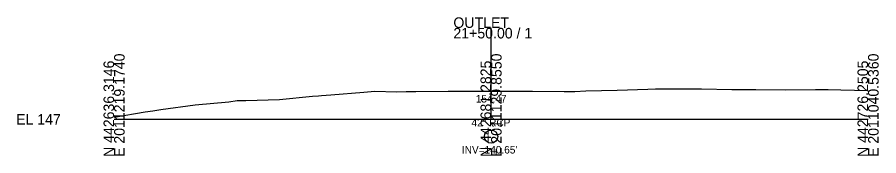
# Model space of a CAD drawing. Extents: x -26 to 1203, y -15 to 9526.
# Drawn here: x 974.3 to 1202.8, y 1490.3 to 1527.1 of the extents above; entities that cross this region are included whole.
import ezdxf

# ---------------------------------------------------------------- set-up
doc = ezdxf.new("R2010")
doc.units = 0
for name, color, linetype in [('Exist Cross Section Cell', 7, 'Continuous'), ('Exist XS Center Line Elevation Label', 7, 'Continuous'), ('Exist XS Ground Line', 7, 'Continuous'), ('Prop XSC Text', 7, 'Continuous')]:
    doc.layers.add(name, color=color, linetype=linetype)

msp = doc.modelspace()

# ---------------------------------------------------------------- linework, layer by layer
at = {"layer": 'Exist Cross Section Cell'}
for p, q in [((1100, 1500), (1100, 1524.3)), ((1000, 1500), (1100, 1500)), ((1100, 1500), (1200, 1500))]:
    msp.add_line(p, q, dxfattribs=at)
at = {"layer": 'Exist XS Ground Line'}
msp.add_lwpolyline([(1000, 1500.59), (1008.2, 1501.96), (1010.27, 1502.29), (1012.38, 1502.57), (1021.47, 1503.87), (1030.43, 1504.68), (1032.66, 1504.96), (1034.92, 1504.97), (1043.86, 1505.27), (1052.67, 1506.13), (1054.26, 1506.27), (1055.05, 1506.35), (1057.47, 1506.5), (1066.25, 1507.25), (1069.15, 1507.52), (1074.91, 1507.33), (1077.45, 1507.38), (1080.02, 1507.39), (1088.64, 1507.49), (1097.15, 1507.48), (1100, 1507.47), (1102.56, 1507.48), (1111.03, 1507.45), (1119.39, 1507.42), (1122.23, 1507.43), (1125.11, 1507.53), (1133.43, 1507.78), (1141.62, 1508.04), (1143.62, 1508.1), (1144.62, 1508.1), (1147.66, 1508.08), (1155.82, 1508.09), (1163.86, 1507.97), (1167.01, 1507.93), (1170.21, 1507.91), (1178.21, 1507.83), (1186.1, 1507.91), (1189.4, 1507.96), (1192.75, 1507.83), (1200, 1507.66)], dxfattribs=at)
at = {"layer": 'Prop XSC Text'}
msp.add_circle((1100, 1495.4), 1.75, dxfattribs=at)

# ---------------------------------------------------------------- texts
at = {"layer": 'Exist Cross Section Cell'}
for s, p in [('OUTLET', (1090, 1524.3)), ('21+50.00 / 1', (1090, 1521.5)), ('EL 147', (974, 1498.6))]:
    msp.add_text(s, height=2.8, dxfattribs=at).set_placement(p)
for s, p in [('N 442636.3146', (1000, 1490)), ('E 2011219.1740', (1002.8, 1490)), ('N 442681.2825', (1100, 1490)), ('E 2011129.8550', (1102.8, 1490)), ('N 442726.2505', (1200, 1490)), ('E 2011040.5360', (1202.8, 1490))]:
    msp.add_text(s, height=2.8, rotation=90, dxfattribs=at).set_placement(p)
at = {"layer": 'Exist XS Center Line Elevation Label'}
msp.add_text('154.47', height=2, dxfattribs=at).set_placement((1095.94, 1504.47))
at = {"layer": 'Prop XSC Text'}
for s, p in [('42" RCP', (1094.81, 1498.12)), ("INV=140.65'", (1092.26, 1490.91))]:
    msp.add_text(s, height=2, dxfattribs=at).set_placement(p)

doc.saveas('drawing.dxf')
